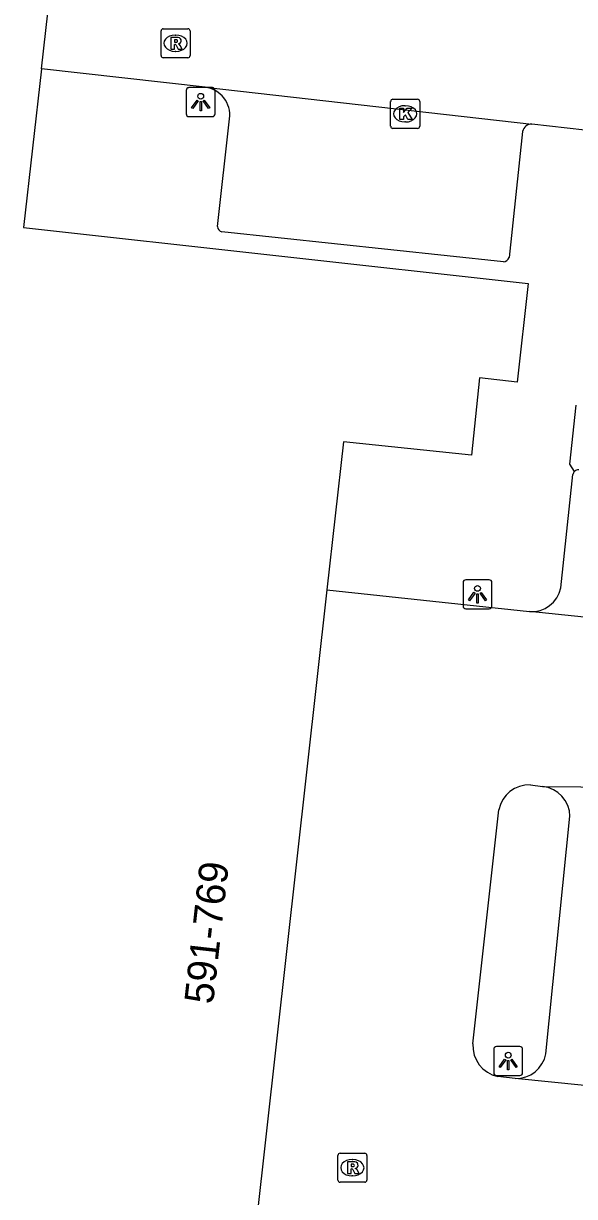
# Model space of a CAD drawing. Extents: x 162026 to 163499, y 387297 to 388169.
# Drawn here: x 162172.21 to 162191.2, y 388074.04 to 388114.47 of the extents above; entities that cross this region are included whole.
import ezdxf

# ---------------------------------------------------------------- set-up
doc = ezdxf.new("R2010")
doc.units = 0
for name, color, linetype in [('IMGEO_Kolk', 7, 'Continuous'), ('IMGEO_Lichtpunt', 7, 'Continuous'), ('IMGEO_Pand', 7, 'Continuous'), ('IMGEO_Pand_nummerreeks', 7, 'Continuous'), ('IMGEO_Parkeervlak_open', 7, 'Continuous'), ('IMGEO_Rijbaan_lokaal_open', 7, 'Continuous'), ('IMGEO_Rioolput', 7, 'Continuous'), ('IMGEO_Voetpad_open', 7, 'Continuous')]:
    doc.layers.add(name, color=color, linetype=linetype)

msp = doc.modelspace()

# ---------------------------------------------------------------- linework, layer by layer
at = {"layer": 'IMGEO_Kolk'}
for p, q in [((162184.937, 388111.852), (162185.789, 388111.852)), ((162184.862, 388110.926), (162184.862, 388111.778)), ((162185.35, 388111.632), (162185.375, 388111.632)), ((162185.863, 388111.778), (162185.863, 388110.926)), ((162185.373, 388111.072), (162185.348, 388111.072)), ((162185.789, 388110.852), (162184.937, 388110.852))]:
    msp.add_line(p, q, dxfattribs=at)
for points in [[(162184.937, 388111.852), (162185.789, 388111.852)], [(162184.862, 388110.926), (162184.862, 388111.778)], [(162185.183, 388111.552), (162185.306, 388111.552), (162185.306, 388111.401), (162185.436, 388111.552), (162185.6, 388111.552), (162185.454, 388111.401), (162185.607, 388111.152), (162185.455, 388111.152), (162185.37, 388111.316), (162185.306, 388111.249), (162185.306, 388111.152), (162185.183, 388111.152), (162185.183, 388111.552)], [(162185.863, 388111.778), (162185.863, 388110.926)], [(162185.789, 388110.852), (162184.937, 388110.852)]]:
    msp.add_lwpolyline(points, dxfattribs=at)
for centre, start, end in [((162184.939, 388111.776), 91.552, 178.448), ((162184.939, 388111.776), 91.552, 178.448), ((162185.787, 388111.776), 1.552, 88.448), ((162185.787, 388111.776), 1.552, 88.448), ((162184.939, 388110.928), 181.552, 268.448), ((162184.939, 388110.928), 181.552, 268.448), ((162185.787, 388110.928), 271.552, 358.448), ((162185.787, 388110.928), 271.552, 358.448)]:
    msp.add_arc(centre, 0.0765, start, end, dxfattribs=at)
for centre, major_axis, ratio, start_param, end_param in [((162185.349, 388111.352), (-0.387, 0.002), 0.722429, 4.712389, 7.853982), ((162185.374, 388111.352), (-0.39, 0.002), 0.717154, 1.570796, 4.712389)]:
    msp.add_ellipse(centre, major_axis=major_axis, ratio=ratio, start_param=start_param, end_param=end_param, dxfattribs=at)
at = {"layer": 'IMGEO_Lichtpunt'}
for p, q in [((162178.719, 388112.254), (162177.911, 388112.254)), ((162178.719, 388112.254), (162177.911, 388112.254)), ((162177.817, 388112.159), (162177.817, 388111.352)), ((162177.817, 388112.159), (162177.817, 388111.352)), ((162178.813, 388111.352), (162178.813, 388112.159)), ((162178.813, 388111.352), (162178.813, 388112.159)), ((162177.911, 388111.258), (162178.719, 388111.258)), ((162177.911, 388111.258), (162178.719, 388111.258)), ((162188.258, 388095.292), (162187.45, 388095.292)), ((162188.258, 388095.292), (162187.45, 388095.292)), ((162187.356, 388095.197), (162187.356, 388094.39)), ((162187.356, 388095.197), (162187.356, 388094.39)), ((162188.352, 388094.39), (162188.352, 388095.197)), ((162188.352, 388094.39), (162188.352, 388095.197)), ((162187.45, 388094.296), (162188.258, 388094.296)), ((162187.45, 388094.296), (162188.258, 388094.296)), ((162188.414, 388079.11), (162188.414, 388078.303)), ((162188.414, 388079.11), (162188.414, 388078.303)), ((162189.316, 388079.205), (162188.508, 388079.205)), ((162189.316, 388079.205), (162188.508, 388079.205)), ((162189.41, 388078.303), (162189.41, 388079.11)), ((162189.41, 388078.303), (162189.41, 388079.11)), ((162188.508, 388078.209), (162189.316, 388078.209)), ((162188.508, 388078.209), (162189.316, 388078.209))]:
    msp.add_line(p, q, dxfattribs=at)
for points in [[(162178.191, 388111.823), (162178.23, 388111.795), (162178.042, 388111.533), (162178.004, 388111.56), (162178.191, 388111.823)], [(162178.403, 388111.795), (162178.441, 388111.822), (162178.628, 388111.56), (162178.589, 388111.532), (162178.403, 388111.795)], [(162178.293, 388111.775), (162178.34, 388111.775), (162178.34, 388111.453), (162178.293, 388111.453), (162178.293, 388111.775)], [(162187.73, 388094.861), (162187.769, 388094.833), (162187.581, 388094.571), (162187.543, 388094.598), (162187.73, 388094.861)], [(162187.942, 388094.833), (162187.98, 388094.86), (162188.167, 388094.598), (162188.128, 388094.57), (162187.942, 388094.833)], [(162187.832, 388094.813), (162187.879, 388094.813), (162187.879, 388094.491), (162187.832, 388094.491), (162187.832, 388094.813)], [(162188.788, 388078.774), (162188.827, 388078.746), (162188.639, 388078.484), (162188.601, 388078.511), (162188.788, 388078.774)], [(162188.89, 388078.726), (162188.937, 388078.726), (162188.937, 388078.404), (162188.89, 388078.404), (162188.89, 388078.726)], [(162189, 388078.746), (162189.038, 388078.773), (162189.225, 388078.511), (162189.186, 388078.483), (162189, 388078.746)]]:
    msp.add_lwpolyline(points, dxfattribs=at)
for centre in [(162178.316, 388111.957), (162187.855, 388094.995), (162188.913, 388078.908)]:
    msp.add_circle(centre, 0.0994, dxfattribs=at)
for centre, start, end in [((162177.911, 388112.159), 90, 180), ((162177.911, 388112.159), 90, 180), ((162178.719, 388112.159), 0, 90), ((162178.719, 388112.159), 0, 90), ((162177.911, 388111.352), 180, 270), ((162177.911, 388111.352), 180, 270), ((162178.719, 388111.352), 270, 0), ((162178.719, 388111.352), 270, 360), ((162187.45, 388095.197), 90, 180), ((162187.45, 388095.197), 90, 180), ((162188.258, 388095.197), 0, 90), ((162188.258, 388095.197), 0, 90), ((162187.45, 388094.39), 180, 270), ((162187.45, 388094.39), 180, 270), ((162188.258, 388094.39), 270, 0), ((162188.258, 388094.39), 270, 360), ((162188.508, 388079.11), 90, 180), ((162188.508, 388079.11), 90, 180), ((162189.316, 388079.11), 0, 90), ((162189.316, 388079.11), 0, 90), ((162188.508, 388078.303), 180, 270), ((162188.508, 388078.303), 180, 270), ((162189.316, 388078.303), 270, 0), ((162189.316, 388078.303), 270, 360)]:
    msp.add_arc(centre, 0.0946, start, end, dxfattribs=at)
at = {"layer": 'IMGEO_Pand'}
for points in [[(162172.827, 388112.903), (162176.16, 388142.394)], [(162172.827, 388112.903), (162172.209, 388107.435), (162189.597, 388105.501), (162189.22, 388102.107), (162187.928, 388102.25), (162187.649, 388099.588), (162183.233, 388100.051), (162182.664, 388094.947)], [(162182.664, 388094.947), (162180.228, 388073.107)]]:
    msp.add_lwpolyline(points, dxfattribs=at)
at = {"layer": 'IMGEO_Parkeervlak_open'}
msp.add_lwpolyline([(162190.21, 388078.953), (162191.041, 388087.141)], dxfattribs=at)
for centre, radius, start, end in [((162191.34, 388098.889), 0.199, 88.1657, 135.3036), ((162189.993, 388087.124), 1.048, 0.928, 84.1838), ((162189.18, 388079.152), 1.049, 268.7388, 349.0833)]:
    msp.add_arc(centre, radius, start, end, dxfattribs=at)
at = {"layer": 'IMGEO_Rijbaan_lokaal_open'}
for points in [[(162178.468, 388112.268), (162172.827, 388112.903)], [(162178.468, 388112.268), (162189.728, 388111.001)], [(162192.161, 388110.716), (162189.728, 388111.001)], [(162182.664, 388094.947), (162189.649, 388094.196)], [(162206.154, 388092.484), (162189.649, 388094.196)], [(162189.683, 388088.223), (162190.099, 388088.167)], [(162190.099, 388088.167), (162191.414, 388088.16), (162206.971, 388086.455)], [(162187.691, 388079.3), (162188.591, 388087.363)], [(162189.157, 388078.103), (162188.553, 388078.173)], [(162208.382, 388076.16), (162189.157, 388078.103)]]:
    msp.add_lwpolyline(points, dxfattribs=at)
for centre, radius, start, end in [((162189.625, 388087.173), 1.052, 86.856, 169.5881), ((162188.788, 388079.246), 1.098, 177.1706, 257.6514)]:
    msp.add_arc(centre, radius, start, end, dxfattribs=at)
at = {"layer": 'IMGEO_Rioolput'}
for p, q in [((162177.024, 388114.284), (162177.876, 388114.284)), ((162176.949, 388113.358), (162176.949, 388114.21)), ((162177.437, 388114.064), (162177.462, 388114.064)), ((162177.95, 388114.21), (162177.95, 388113.358)), ((162177.46, 388113.504), (162177.435, 388113.504)), ((162177.876, 388113.284), (162177.024, 388113.284)), ((162183.042, 388074.605), (162183.042, 388075.457)), ((162183.117, 388075.531), (162183.969, 388075.531)), ((162184.043, 388075.457), (162184.043, 388074.605)), ((162183.53, 388075.311), (162183.555, 388075.311)), ((162183.553, 388074.751), (162183.528, 388074.751)), ((162183.969, 388074.531), (162183.117, 388074.531))]:
    msp.add_line(p, q, dxfattribs=at)
for points in [[(162177.024, 388114.284), (162177.876, 388114.284)], [(162176.949, 388113.358), (162176.949, 388114.21)], [(162177.538, 388113.982), (162177.286, 388113.984), (162177.286, 388113.584)], [(162177.464, 388113.903), (162177.41, 388113.903), (162177.41, 388113.822)], [(162177.41, 388113.822), (162177.462, 388113.822)], [(162177.95, 388114.21), (162177.95, 388113.358)], [(162177.286, 388113.584), (162177.41, 388113.584), (162177.41, 388113.746), (162177.421, 388113.746)], [(162177.468, 388113.717), (162177.539, 388113.584), (162177.679, 388113.584), (162177.614, 388113.71)], [(162177.876, 388113.284), (162177.024, 388113.284)], [(162183.042, 388074.605), (162183.042, 388075.457)], [(162183.117, 388075.531), (162183.969, 388075.531)], [(162184.043, 388075.457), (162184.043, 388074.605)], [(162183.631, 388075.229), (162183.379, 388075.231), (162183.379, 388074.831)], [(162183.557, 388075.15), (162183.503, 388075.15), (162183.503, 388075.069)], [(162183.503, 388075.069), (162183.555, 388075.069)], [(162183.379, 388074.831), (162183.503, 388074.831), (162183.503, 388074.993), (162183.514, 388074.993)], [(162183.561, 388074.964), (162183.632, 388074.831), (162183.772, 388074.831), (162183.707, 388074.957)], [(162183.969, 388074.531), (162183.117, 388074.531)]]:
    msp.add_lwpolyline(points, dxfattribs=at)
for centre, radius, start, end in [((162177.026, 388114.208), 0.0765, 91.552, 178.448), ((162177.026, 388114.208), 0.0765, 91.552, 178.448), ((162177.874, 388114.208), 0.0765, 1.552, 88.448), ((162177.874, 388114.208), 0.0765, 1.552, 88.448), ((162177.446, 388114.011), 0.19, 274.7715, 282.9687), ((162177.47, 388113.807), 0.0964, 77.0061, 93.1865), ((162177.484, 388113.864), 0.0378, 276.6634, 79.6772), ((162177.537, 388113.872), 0.109, 350.3612, 89.416), ((162177.535, 388113.872), 0.112, 277.5842, 350.9817), ((162177.42, 388113.693), 0.0533, 26.0293, 88.6989), ((162177.519, 388113.657), 0.108, 29.5134, 73.7905), ((162177.026, 388113.36), 0.0765, 181.552, 268.448), ((162177.026, 388113.36), 0.0765, 181.552, 268.448), ((162177.874, 388113.36), 0.0765, 271.552, 358.448), ((162177.874, 388113.36), 0.0765, 271.552, 358.448), ((162183.119, 388075.455), 0.0765, 91.552, 178.448), ((162183.119, 388075.455), 0.0765, 91.552, 178.448), ((162183.967, 388075.455), 0.0765, 1.552, 88.448), ((162183.967, 388075.455), 0.0765, 1.552, 88.448), ((162183.539, 388075.258), 0.19, 274.7715, 282.9687), ((162183.563, 388075.054), 0.0964, 77.0061, 93.1865), ((162183.577, 388075.111), 0.0378, 276.6634, 79.6772), ((162183.63, 388075.119), 0.109, 350.3612, 89.416), ((162183.628, 388075.119), 0.112, 277.5842, 350.9817), ((162183.119, 388074.607), 0.0765, 181.552, 268.448), ((162183.119, 388074.607), 0.0765, 181.552, 268.448), ((162183.513, 388074.94), 0.0533, 26.0293, 88.6989), ((162183.612, 388074.904), 0.108, 29.5134, 73.7905), ((162183.967, 388074.607), 0.0765, 271.552, 358.448), ((162183.967, 388074.607), 0.0765, 271.552, 358.448)]:
    msp.add_arc(centre, radius, start, end, dxfattribs=at)
for centre, major_axis, ratio, start_param, end_param in [((162177.436, 388113.784), (-0.387, 0.002), 0.722429, 4.712389, 7.853982), ((162177.461, 388113.784), (-0.39, 0.002), 0.717154, 1.570796, 4.712389), ((162183.529, 388075.031), (-0.387, 0.002), 0.722429, 4.712389, 7.853982), ((162183.554, 388075.031), (-0.39, 0.002), 0.717154, 1.570796, 4.712389)]:
    msp.add_ellipse(centre, major_axis=major_axis, ratio=ratio, start_param=start_param, end_param=end_param, dxfattribs=at)
at = {"layer": 'IMGEO_Voetpad_open'}
for points in [[(162178.895, 388107.467), (162179.312, 388111.181)], [(162189.403, 388110.747), (162188.944, 388106.404)], [(162188.746, 388106.254), (162179.043, 388107.281)], [(162191.198, 388099.029), (162191.035, 388099.282), (162191.252, 388101.313)], [(162190.725, 388095.015), (162191.145, 388098.919)]]:
    msp.add_lwpolyline(points, dxfattribs=at)
for centre, radius, start, end in [((162178.342, 388111.299), 0.977, 353.081, 82.574), ((162189.742, 388110.648), 0.353, 92.2911, 163.7269), ((162179.108, 388107.484), 0.214, 184.6872, 252.3313), ((162188.732, 388106.478), 0.224, 273.4756, 340.8178), ((162191.346, 388098.89), 0.203, 136.7797, 171.7691), ((162189.717, 388095.223), 1.029, 266.1914, 348.3619)]:
    msp.add_arc(centre, radius, start, end, dxfattribs=at)

# ---------------------------------------------------------------- texts
at = {"layer": 'IMGEO_Pand_nummerreeks'}
msp.add_text('591-769', height=1, rotation=83.606, dxfattribs=at).set_placement((162178.741, 388080.642))

doc.saveas('drawing.dxf')
